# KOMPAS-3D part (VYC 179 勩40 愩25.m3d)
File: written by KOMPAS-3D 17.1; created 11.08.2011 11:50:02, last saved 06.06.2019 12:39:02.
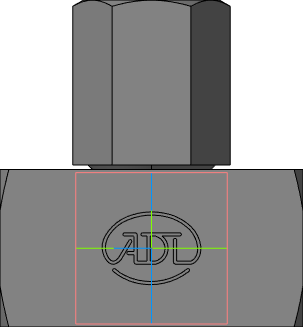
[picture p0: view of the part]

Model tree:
1. Плоскость XY
2. Плоскость ZX
3. Плоскость ZY
4. Ось X
5. Ось Y
6. Ось Z
7. Начало координат
8. Операция без истории:2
